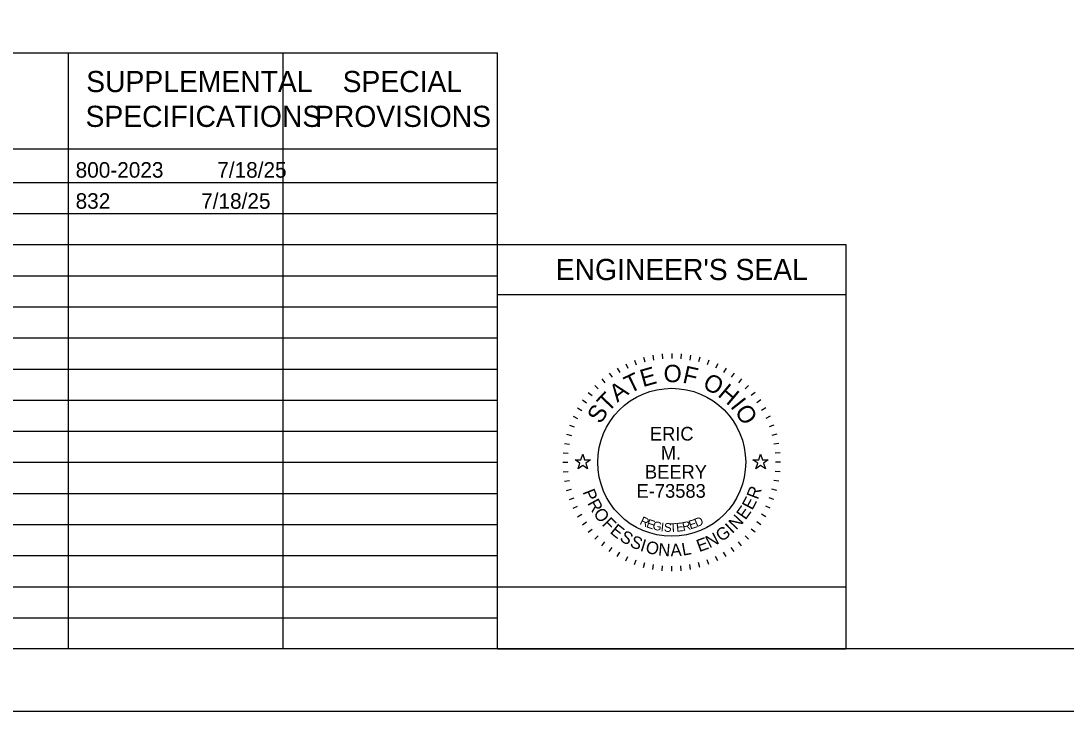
# Model space of a CAD drawing. Extents: x 0 to 34, y 0 to 22.
# Drawn here: x 19.77 to 28.17, y 0 to 5.55 of the extents above; entities that cross this region are included whole.
import ezdxf

# ---------------------------------------------------------------- set-up
doc = ezdxf.new("R2010")
doc.units = 0
for name, color, linetype in [('Default', 7, 'Continuous'), ('SH_Border', 7, 'Continuous'), ('SH_Cut_Line', 7, 'Continuous'), ('SH_Data', 7, 'Continuous'), ('SH_Text', 7, 'Continuous')]:
    doc.layers.add(name, color=color, linetype=linetype)

msp = doc.modelspace()

# ---------------------------------------------------------------- linework, layer by layer
at = {"layer": 'Default'}
for points in [[(24.2236, 2.02), (24.2705, 2.02), (24.285, 2.0645), (24.2995, 2.02), (24.3464, 2.02), (24.3085, 1.9924), (24.323, 1.9478), (24.285, 1.9754), (24.247, 1.9478), (24.2615, 1.9924)], [(25.6536, 2.02), (25.7005, 2.02), (25.715, 2.0645), (25.7295, 2.02), (25.7764, 2.02), (25.7385, 1.9924), (25.753, 1.9478), (25.715, 1.9754), (25.677, 1.9478), (25.6915, 1.9924)]]:
    msp.add_lwpolyline(points, close=True, dxfattribs=at)
at = {"layer": 'SH_Border'}
msp.add_lwpolyline([(1.5, 21.5), (33.5, 21.5), (33.5, 0.5), (1.5, 0.5)], close=True, dxfattribs=at)
at = {"layer": 'SH_Cut_Line'}
msp.add_lwpolyline([(0, 0), (34, 0), (34, 22), (0, 22)], close=True, dxfattribs=at)
at = {"layer": 'SH_Data'}
for p, q in [((10.15, 5.2917), (23.6, 5.2917)), ((20.15, 0.5), (20.15, 5.2917)), ((21.875, 0.5), (21.875, 5.2917)), ((23.6, 0.5), (23.6, 5.2917)), ((10.15, 4.5209), (23.6, 4.5209)), ((10.15, 4.25), (23.6, 4.25)), ((10.15, 4), (23.6, 4)), ((10.15, 3.75), (23.6, 3.75)), ((23.6, 0.5), (23.6, 3.75)), ((23.6, 3.75), (26.4, 3.75)), ((26.4, 3.75), (26.4, 0.5)), ((10.15, 3.5), (23.6, 3.5)), ((23.6, 3.35), (26.4, 3.35)), ((10.15, 3.25), (23.6, 3.25)), ((10.15, 3), (23.6, 3)), ((24.8481, 2.8617), (24.855, 2.8223)), ((24.9237, 2.8717), (24.9272, 2.8318)), ((25, 2.875), (25, 2.835)), ((25.0763, 2.8717), (25.0728, 2.8318)), ((25.1519, 2.8617), (25.145, 2.8223)), ((24.6302, 2.793), (24.6471, 2.7568)), ((24.7007, 2.8222), (24.7144, 2.7846)), ((24.7735, 2.8452), (24.7839, 2.8065)), ((25.2265, 2.8452), (25.2161, 2.8065)), ((25.2993, 2.8222), (25.2856, 2.7846)), ((25.3698, 2.793), (25.3529, 2.7568)), ((10.15, 2.75), (23.6, 2.75)), ((24.4981, 2.7168), (24.5211, 2.684)), ((24.5625, 2.7578), (24.5825, 2.7231)), ((25.4375, 2.7578), (25.4175, 2.7231)), ((25.5019, 2.7168), (25.4789, 2.684)), ((24.3813, 2.6187), (24.4096, 2.5904)), ((24.4376, 2.6703), (24.4633, 2.6396)), ((25.5624, 2.6703), (25.5367, 2.6396)), ((25.6187, 2.6187), (25.5904, 2.5904)), ((24.3297, 2.5624), (24.3604, 2.5367)), ((25.6703, 2.5624), (25.6396, 2.5367)), ((10.15, 2.5), (23.6, 2.5)), ((24.2422, 2.4375), (24.2769, 2.4175)), ((24.2832, 2.5019), (24.316, 2.4789)), ((25.7168, 2.5019), (25.684, 2.4789)), ((25.7578, 2.4375), (25.7231, 2.4175)), ((24.207, 2.3698), (24.2432, 2.3529)), ((25.793, 2.3698), (25.7568, 2.3529)), ((24.1778, 2.2993), (24.2154, 2.2856)), ((25.8222, 2.2993), (25.7846, 2.2856)), ((10.15, 2.25), (23.6, 2.25)), ((24.1548, 2.2265), (24.1935, 2.2161)), ((25.8452, 2.2265), (25.8065, 2.2161)), ((24.1383, 2.1519), (24.1777, 2.145)), ((25.8617, 2.1519), (25.8223, 2.145)), ((24.1283, 2.0763), (24.1682, 2.0728)), ((25.8717, 2.0763), (25.8318, 2.0728)), ((10.15, 2), (23.6, 2)), ((24.125, 2), (24.165, 2)), ((25.875, 2), (25.835, 2)), ((24.1283, 1.9237), (24.1682, 1.9272)), ((24.1383, 1.8481), (24.1777, 1.855)), ((25.8617, 1.8481), (25.8223, 1.855)), ((25.8717, 1.9237), (25.8318, 1.9272)), ((24.1548, 1.7735), (24.1935, 1.7839)), ((25.8452, 1.7735), (25.8065, 1.7839)), ((10.15, 1.75), (23.6, 1.75)), ((24.1778, 1.7007), (24.2154, 1.7144)), ((25.8222, 1.7007), (25.7846, 1.7144)), ((24.207, 1.6302), (24.2432, 1.6471)), ((25.793, 1.6302), (25.7568, 1.6471)), ((24.2422, 1.5625), (24.2769, 1.5825)), ((24.2832, 1.4981), (24.316, 1.5211)), ((25.7168, 1.4981), (25.684, 1.5211)), ((25.7578, 1.5625), (25.7231, 1.5825)), ((10.15, 1.5), (23.6, 1.5)), ((24.3297, 1.4376), (24.3604, 1.4633)), ((25.6703, 1.4376), (25.6396, 1.4633)), ((24.3813, 1.3813), (24.4096, 1.4096)), ((24.4376, 1.3297), (24.4633, 1.3604)), ((25.5624, 1.3297), (25.5367, 1.3604)), ((25.6187, 1.3813), (25.5904, 1.4096)), ((24.4981, 1.2832), (24.5211, 1.316)), ((24.5625, 1.2422), (24.5825, 1.2769)), ((25.4375, 1.2422), (25.4175, 1.2769)), ((25.5019, 1.2832), (25.4789, 1.316)), ((10.15, 1.25), (23.6, 1.25)), ((24.6302, 1.207), (24.6471, 1.2432)), ((24.7007, 1.1778), (24.7144, 1.2154)), ((24.7735, 1.1548), (24.7839, 1.1935)), ((24.8481, 1.1383), (24.855, 1.1777)), ((25.1519, 1.1383), (25.145, 1.1777)), ((25.2265, 1.1548), (25.2161, 1.1935)), ((25.2993, 1.1778), (25.2856, 1.2154)), ((25.3698, 1.207), (25.3529, 1.2432)), ((24.9237, 1.1283), (24.9272, 1.1682)), ((25, 1.125), (25, 1.165)), ((25.0763, 1.1283), (25.0728, 1.1682)), ((10.15, 1), (23.6, 1)), ((10.15, 0.75), (23.6, 0.75)), ((23.6, 0.5), (26.4, 0.5))]:
    msp.add_line(p, q, dxfattribs=at)
msp.add_lwpolyline([(23.6, 0.5), (23.6, 1), (26.4, 1), (26.4, 0.5)], close=True, dxfattribs=at)
msp.add_circle((25, 2), 0.595, dxfattribs=at)

# ---------------------------------------------------------------- texts
at = {"layer": 'Default'}
for s, p in [('800-2023', (20.2072, 4.2883)), ('7/18/25', (21.3461, 4.2883)), ('832', (20.2072, 4.0383)), ('7/18/25', (21.2166, 4.0383))]:
    msp.add_text(s, height=0.125, dxfattribs=at).set_placement(p)
at = {"layer": 'SH_Data'}
for s, height, p in [("ENGINEER'S SEAL", 0.17, (24.0676, 3.465)), ('ERIC ', 0.11, (24.8244, 2.1749)), ('M.', 0.11, (24.9126, 2.0216)), ('BEERY', 0.11, (24.7848, 1.8684)), ('E-73583', 0.11, (24.7177, 1.7151))]:
    msp.add_text(s, height=height, dxfattribs=at).set_placement(p)
for s, height, rotation, p in [('O', 0.14, 359.78119, (24.9347, 2.6443)), ('F', 0.14, 347.43619, (25.0811, 2.6417)), ('T', 0.14, 25.71674, (24.6616, 2.5518)), ('E', 0.14, 15.75706, (24.7684, 2.6038)), ('O', 0.14, 332.25863, (25.2398, 2.6015)), ('A', 0.14, 36.47472, (24.5634, 2.4781)), ('H', 0.14, 319.91363, (25.3632, 2.5361)), ('T', 0.14, 46.4344, (24.4883, 2.3964)), ('I', 0.14, 308.36695, (25.4665, 2.4483)), ('S', 0.14, 57.19238, (24.4281, 2.3014)), ('O', 0.14, 303.14906, (25.5021, 2.4089)), ('P', 0.1, 291.49398, (24.2823, 1.7621)), ('R', 0.1, 69.23216, (25.6919, 1.6954)), ('R', 0.1, 298.73106, (24.319, 1.6717)), ('E', 0.1, 61.99508, (25.6476, 1.6098)), ('O', 0.1, 306.46664, (24.3655, 1.5883)), ('E', 0.1, 54.75801, (25.5933, 1.5314)), ('F', 0.1, 314.7068, (24.4343, 1.4983)), ('R', 0.07, 334.48695, (24.7375, 1.5051)), ('E', 0.07, 341.03996, (24.7906, 1.4801)), ('G', 0.07, 347.47515, (24.8414, 1.4618)), ('I', 0.07, 353.78581, (24.9091, 1.4468)), ('S', 0.07, 356.89262, (24.9358, 1.4429)), ('E', 0.07, 6.01169, (25.0389, 1.4412)), ('R', 0.07, 11.91844, (25.0925, 1.4474)), ('E', 0.07, 17.68363, (25.1498, 1.4602)), ('D', 0.07, 23.30524, (25.201, 1.477)), ('N', 0.1, 47.02243, (25.5202, 1.4508)), ('E', 0.1, 321.43929, (24.4978, 1.4348)), ('S', 0.1, 328.67637, (24.5743, 1.3752)), ('T', 0.07, 3.00609, (24.9857, 1.4387)), ('N', 0.1, 27.31129, (25.3045, 1.3075)), ('G', 0.1, 35.04687, (25.3981, 1.357)), ('I', 0.1, 43.28703, (25.4868, 1.4214)), ('S', 0.1, 335.91345, (24.6564, 1.3266)), ('I', 0.1, 343.15053, (24.7406, 1.2897)), ('O', 0.1, 346.88592, (24.7839, 1.2751)), ('N', 0.1, 355.12608, (24.8888, 1.2517)), ('A', 0.1, 2.86166, (24.9923, 1.2437)), ('L', 0.1, 10.09874, (25.0894, 1.249)), ('E', 0.1, 20.07421, (25.2212, 1.277))]:
    msp.add_text(s, height=height, rotation=rotation, dxfattribs=at).set_placement(p)
at = {"layer": 'SH_Text'}
for s, p in [('SUPPLEMENTAL', (20.2925, 4.9763)), ('SPECIAL', (22.3542, 4.9763)), ('SPECIFICATIONS', (20.2871, 4.6963)), ('PROVISIONS', (22.1323, 4.6963))]:
    msp.add_text(s, height=0.17, dxfattribs=at).set_placement(p)

doc.saveas('drawing.dxf')
